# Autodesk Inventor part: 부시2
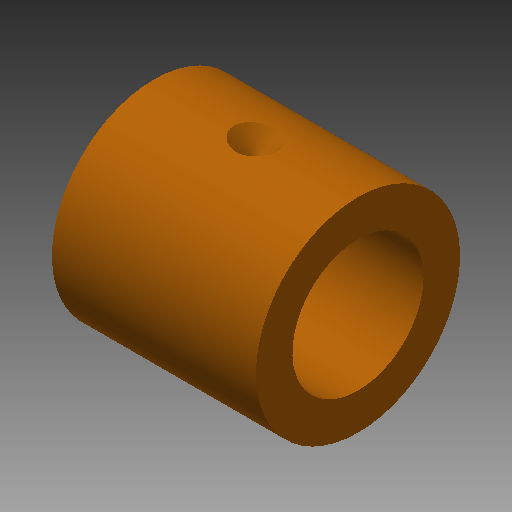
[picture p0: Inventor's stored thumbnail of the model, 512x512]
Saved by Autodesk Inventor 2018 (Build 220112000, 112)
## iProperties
Created: 2020-03
Part Number: 부시2
Material: 스테인리스강
Document SubType Name: Modeling
Designer: mduedu
Density: 8.08 g/cm^3
Appearance: 주황색
Mass: 10.1904 g
Surface Area: 11.9485 cm^2
Volume: 1.26119 cm^3
Author: mduedu
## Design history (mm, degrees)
sketch "스케치2"
  geometry: C1 r 7 at (0, 0); C2 r 4.5 at (0, 0); 1 further point
  constraints: 2 centre point, 2 coincident
  dimensions: "d15" = 14 diameter of C1; "d16" = 9 diameter of C2
extrude "돌출1" new body sketch "스케치2" distance "d17" = 14; taper "d18" = 0 deg
sketch "스케치3"
  geometry: L1 (0, -7)-(-14, -7) reference; L2 (-14, -7)-(-14, -4.5) reference; L3 (-14, -4.5)-(0, -4.5) reference; L4 (0, -4.5)-(0, -7) reference; L5 (-14, 7)-(0, 7) reference; L6 (0, 7)-(0, 4.5) reference; L7 (0, 4.5)-(-14, 4.5) reference; L8 (-14, 4.5)-(-14, 7) reference; L9 (-7, 7)-(-7, 5.5); L10 (-7, 5.5)-(-5.5, 7); L11 (-5.5, 7)-(-7, 7); 1 further point
  constraints: 6 end point, 1 collinear, 1 midpoint, 1 parallel, 1 point on line
  dimensions: "d19" = 3 diameter of L10.end L9; "d21" = 7 distance between parallel lines of L6 L9; "d22" = 45 deg angle of L10 L9
revolve "회전2" sketch "스케치3" stored, may be unused: angle "d23" = 90 deg
node "작업점1"
node "솔리드2"
node "절단 모서리 투영1"
